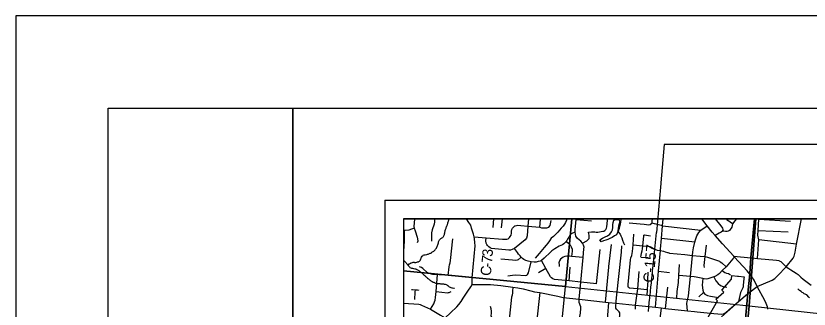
# Model space of a CAD drawing. Extents: x -8.2 to 38.5, y -0.1 to 21.9.
# Drawn here: x 0.063 to 4.362, y 20.274 to 21.864 of the extents above; entities that cross this region are included whole.
import ezdxf

# ---------------------------------------------------------------- set-up
doc = ezdxf.new("R2010")
doc.units = 0
for name, color, linetype in [('Default', 7, 'Continuous'), ('GM_X_Adjacent_County_Text', 7, 'Continuous'), ('GM_X_Airport_Location_Class_2', 7, 'Continuous'), ('GM_X_Airport_Location_Class_3', 7, 'Continuous'), ('GM_X_County', 7, 'Continuous'), ('GM_X_Minor_Lake', 7, 'Continuous'), ('GM_X_Minor_Lake_Text', 7, 'Continuous'), ('GM_X_Minor_River', 7, 'Continuous'), ('GM_X_Section', 7, 'Continuous'), ('GM_X_Township', 7, 'Continuous'), ('GM_X_Township_Subdivision_Text', 7, 'Continuous'), ('GM_X_Township_Text', 7, 'Continuous')]:
    doc.layers.add(name, color=color, linetype=linetype)

msp = doc.modelspace()

# ---------------------------------------------------------------- linework, layer by layer
at = {"layer": 'Default'}
for points in [[(8.9634, 21.1673), (3.5768, 21.1673), (3.5587, 20.9592), (3.5579, 20.9504), (3.5571, 20.9409), (3.557, 20.9403), (3.5565, 20.9346), (3.5354, 20.6894), (3.5327, 20.6897), (3.5152, 20.5087), (3.514, 20.4975), (3.5122, 20.481), (3.5118, 20.4768), (3.5106, 20.466), (3.5092, 20.4518), (3.5081, 20.4422), (3.5079, 20.44), (3.5067, 20.4286), (3.5055, 20.4169), (3.5042, 20.4045), (3.5032, 20.3958), (3.5024, 20.388), (3.5012, 20.3763), (3.4999, 20.3644), (3.4987, 20.3529), (3.4972, 20.3387), (3.4965, 20.3322), (3.4956, 20.3236), (3.494, 20.3078), (3.4939, 20.3071), (3.4918, 20.2869), (3.489, 20.2612)], [(3.7486, 17.3899), (3.8184, 18.0516), (3.8435, 18.2895), (3.8449, 18.303), (3.8472, 18.3279), (3.8854, 18.7517), (3.9289, 19.2353), (3.9436, 19.3979), (3.9961, 19.9817), (4.0302, 20.3597), (4.0404, 20.4649), (4.0467, 20.5533), (4.0665, 20.7635), (4.0666, 20.7645), (2.1634, 20.7645), (2.1634, 15.4317)], [(8.9634, 15.3136), (8.9634, 20.7535), (8.8842, 20.7645), (4.0666, 20.7645), (4.0665, 20.7635), (4.0467, 20.5533), (4.0404, 20.4649), (4.0302, 20.3597), (3.9961, 19.9817), (3.9436, 19.3979), (3.9289, 19.2353), (3.8854, 18.7517), (3.8472, 18.3279), (3.8449, 18.303), (3.8435, 18.2895), (3.8184, 18.0516), (3.7486, 17.3899)], [(3.8148, 20.2303), (3.8651, 20.3183), (3.859, 20.3257), (3.8572, 20.3279), (3.8855, 20.353), (3.8997, 20.3656), (3.8894, 20.3771), (3.9415, 20.4374), (3.9437, 20.456), (3.9743, 20.4531), (3.9791, 20.4526), (4.0097, 20.4497), (4.0088, 20.4408), (4.0086, 20.4392), (4.005, 20.4034), (4.0044, 20.3971), (4.0042, 20.3951), (4.0036, 20.3893), (3.9899, 20.3651), (3.98, 20.3157), (3.9795, 20.3133), (3.8874, 20.2316)]]:
    msp.add_lwpolyline(points, dxfattribs=at)
for points in [[(3.0765, 20.7645), (2.1634, 20.7645), (2.1634, 20.4819), (3.0413, 20.3975)], [(4.0738, 20.7645), (3.0765, 20.7645), (3.0413, 20.3975), (4.0367, 20.2914)], [(5.1033, 20.7645), (4.0738, 20.7645), (4.0367, 20.2914), (5.0467, 20.1811)], [(2.1634, 20.4819), (2.1634, 19.4712), (2.9408, 19.3823), (3.0413, 20.3975)]]:
    msp.add_lwpolyline(points, close=True, dxfattribs=at)
at = {"layer": 'GM_X_Adjacent_County_Text'}
for points in [[(3.0413, 20.3975), (4.0367, 20.2914), (3.9431, 19.2991), (2.9408, 19.3823)], [(5.0467, 20.1811), (4.9457, 19.1792), (3.9431, 19.2991), (4.0367, 20.2914)]]:
    msp.add_lwpolyline(points, close=True, dxfattribs=at)
at = {"layer": 'GM_X_Airport_Location_Class_2'}
for p, q in [((2.6514, 20.7645), (2.6475, 20.7165)), ((2.6989, 20.7645), (2.6941, 20.7153)), ((2.9021, 20.7177), (2.9058, 20.7604)), ((3.0994, 20.7593), (3.1835, 20.7536)), ((2.1634, 20.6425), (2.1676, 20.6423)), ((3.2101, 20.4104), (3.2288, 20.5982)), ((2.9357, 20.495), (2.8955, 20.47)), ((3.0619, 20.4273), (3.0678, 20.5019)), ((3.2583, 20.3122), (3.2772, 20.5021)), ((3.2757, 20.3104), (3.2633, 20.1713))]:
    msp.add_line(p, q, dxfattribs=at)
for points in [[(2.2235, 20.7645), (2.2215, 20.7396), (2.2202, 20.7231), (2.2221, 20.7122), (2.2268, 20.6995), (2.2377, 20.6645), (2.2405, 20.6553), (2.2408, 20.642), (2.2387, 20.6341)], [(2.3333, 20.7645), (2.3325, 20.7561), (2.3318, 20.7476), (2.3307, 20.7345), (2.3198, 20.7033), (2.3163, 20.6871), (2.3162, 20.6712), (2.315, 20.6587), (2.3157, 20.6427)], [(2.8422, 20.7645), (2.8382, 20.7234), (2.8333, 20.6724), (2.8299, 20.6584), (2.8236, 20.6495), (2.7647, 20.6033), (2.7531, 20.5967), (2.7441, 20.594), (2.7345, 20.5935), (2.6409, 20.6035), (2.6336, 20.6065), (2.6271, 20.6112), (2.6194, 20.6184), (2.615, 20.6249), (2.6115, 20.6314), (2.6103, 20.6441), (2.6117, 20.6611)], [(3.1167, 20.328), (3.1251, 20.4205), (3.1369, 20.5541), (3.1419, 20.6014), (3.1425, 20.6102), (3.139, 20.6215), (3.1331, 20.6312), (3.1241, 20.6432), (3.1064, 20.6577), (3.0987, 20.6704), (3.0938, 20.6911), (3.0947, 20.704), (3.0994, 20.7593), (3.0998, 20.7645)], [(3.1331, 20.6312), (3.1581, 20.6447), (3.1654, 20.651), (3.1702, 20.6571), (3.1698, 20.6666), (3.1697, 20.6758), (3.168, 20.683), (3.1668, 20.6922), (3.1834, 20.6933), (3.1942, 20.6933), (3.2003, 20.6927), (3.208, 20.6919), (3.213, 20.6915), (3.2178, 20.6919), (3.2447, 20.696), (3.25, 20.6977), (3.2541, 20.6998), (3.2574, 20.7025), (3.26, 20.7054), (3.2626, 20.7094), (3.2645, 20.7139), (3.266, 20.7203), (3.2695, 20.7542), (3.2698, 20.7585), (3.2695, 20.7612), (3.2683, 20.7645)], [(3.5112, 20.7409), (3.5119, 20.7512), (3.513, 20.7645)], [(2.5468, 20.6666), (2.6117, 20.6611), (2.7, 20.6541), (2.7129, 20.6531), (2.7242, 20.6541), (2.7315, 20.6559), (2.7379, 20.6616), (2.7427, 20.6671), (2.7467, 20.6758), (2.7485, 20.6851), (2.7498, 20.6977), (2.7516, 20.705), (2.7524, 20.7094), (2.7546, 20.7136), (2.7584, 20.7174), (2.7616, 20.7212), (2.7678, 20.725)], [(2.7678, 20.725), (2.7685, 20.7255), (2.7766, 20.7281), (2.7829, 20.7287), (2.7989, 20.7281), (2.8382, 20.7234), (2.9021, 20.7177), (2.9124, 20.7157), (2.9238, 20.7147), (2.9347, 20.7145), (2.9408, 20.7151), (2.9519, 20.7193), (2.9588, 20.7272), (2.9612, 20.7361), (2.9647, 20.7547)], [(3.5112, 20.7409), (3.501, 20.732), (3.4934, 20.7295), (3.4815, 20.7311), (3.4675, 20.7322), (3.4473, 20.7344), (3.3876, 20.7403)], [(3.5683, 20.7261), (3.5242, 20.7363), (3.5112, 20.7409)], [(2.2221, 20.7122), (2.1926, 20.7031), (2.1747, 20.701), (2.1682, 20.7014), (2.1634, 20.7017)], [(2.1682, 20.7014), (2.1676, 20.6423), (2.1634, 20.5891)], [(3.0938, 20.6911), (3.0792, 20.6866), (3.0717, 20.6815), (3.0671, 20.6772), (3.0592, 20.6649), (3.0528, 20.6531), (3.0511, 20.6496)], [(3.4842, 20.3782), (3.4325, 20.3839), (3.3878, 20.3881), (3.3825, 20.3918), (3.3814, 20.3964), (3.382, 20.4075), (3.392, 20.522), (3.3943, 20.5412), (3.3962, 20.5518), (3.4004, 20.5641), (3.4051, 20.5863), (3.4092, 20.6236), (3.4118, 20.6807)], [(2.4063, 20.4569), (2.4108, 20.5026), (2.4135, 20.5151), (2.4173, 20.5244), (2.4189, 20.5377), (2.431, 20.6555)], [(3.0511, 20.6496), (3.0495, 20.646), (3.0459, 20.6403), (3.0337, 20.6277), (3.0249, 20.6224), (3.0074, 20.6149), (2.9832, 20.6017), (2.968, 20.5901), (2.9598, 20.5835), (2.9256, 20.5502), (2.9114, 20.5385), (2.9039, 20.5343), (2.8943, 20.5316), (2.8833, 20.5296), (2.8712, 20.5296), (2.8554, 20.5313), (2.8398, 20.5346), (2.8276, 20.5379), (2.8158, 20.5435), (2.8089, 20.548), (2.8015, 20.5553), (2.7956, 20.5636), (2.7877, 20.5725), (2.7814, 20.5816), (2.7647, 20.6033)], [(3.0459, 20.6403), (3.0573, 20.6318), (3.0663, 20.6226), (3.0729, 20.6114), (3.0772, 20.599), (3.0775, 20.5882), (3.0751, 20.5601)], [(3.4894, 20.553), (3.4522, 20.5549), (3.4507, 20.5583), (3.4522, 20.5644), (3.4543, 20.5782), (3.4566, 20.5896), (3.4599, 20.6013), (3.4617, 20.6172), (3.4658, 20.67), (3.4668, 20.6746), (3.4697, 20.6764), (3.5028, 20.6718)], [(3.2772, 20.5021), (3.2775, 20.5051), (3.2912, 20.6254)], [(3.3169, 20.3159), (3.3186, 20.3349), (3.3448, 20.5828), (3.3479, 20.6175)], [(3.4092, 20.6236), (3.4617, 20.6172), (3.4873, 20.6153), (3.4989, 20.6133), (3.5076, 20.6099), (3.5187, 20.6031), (3.5292, 20.5967), (3.5378, 20.5939), (3.556, 20.5928)], [(2.8015, 20.5553), (2.7855, 20.5415), (2.7803, 20.5388), (2.7714, 20.5376), (2.7549, 20.5391), (2.691, 20.5444)], [(3.1369, 20.5541), (3.0751, 20.5601), (3.0634, 20.561), (3.0487, 20.5616), (3.0388, 20.5595), (3.0298, 20.5558), (3.0215, 20.5509), (3.0147, 20.5448), (3.009, 20.5365), (3.0063, 20.5255), (3.0071, 20.5161), (3.0084, 20.5052)], [(2.7298, 20.4539), (2.754, 20.4576), (2.7714, 20.4597), (2.8275, 20.4562), (2.8317, 20.458), (2.8356, 20.4613), (2.8415, 20.4707), (2.8554, 20.5313)], [(3.2101, 20.4104), (3.1251, 20.4205), (3.0619, 20.4273), (2.9829, 20.4355), (2.9735, 20.4381), (2.9661, 20.4438), (2.9614, 20.4497), (2.9357, 20.495), (2.9114, 20.5385)], [(2.3581, 20.4607), (2.3485, 20.4612), (2.3226, 20.4616), (2.3031, 20.4667), (2.2926, 20.4729), (2.2691, 20.4944), (2.2612, 20.4995), (2.2506, 20.5027)], [(3.4393, 20.4772), (3.4325, 20.3839), (3.4194, 20.2958)], [(3.4878, 20.4745), (3.4854, 20.4338), (3.4881, 20.4243), (3.4867, 20.4082), (3.4842, 20.3782), (3.4817, 20.3482)], [(2.3101, 20.2742), (2.3284, 20.3026), (2.3325, 20.3137), (2.3347, 20.3228), (2.3373, 20.3376), (2.3402, 20.3699), (2.3485, 20.4612)], [(2.5364, 20.4439), (2.4063, 20.4569), (2.3782, 20.4597), (2.3581, 20.4607)], [(2.7563, 20.3938), (2.7551, 20.3718), (2.7545, 20.363), (2.7524, 20.3494), (2.749, 20.3391), (2.7302, 20.1485)], [(2.3402, 20.3699), (2.4016, 20.3631), (2.4077, 20.3637), (2.4111, 20.3651), (2.4215, 20.3705)], [(2.9036, 20.3635), (2.8852, 20.2003), (2.8761, 20.1127), (2.8707, 20.0414)], [(3.0263, 20.1974), (3.0546, 20.1948), (3.0702, 20.1932), (3.0822, 20.1942), (3.1012, 20.2028), (3.1098, 20.2103), (3.1169, 20.2221), (3.1202, 20.2344), (3.1224, 20.2523), (3.1252, 20.2786), (3.1245, 20.2864), (3.1158, 20.3093), (3.1155, 20.3179), (3.1167, 20.328)], [(3.325, 20.1305), (3.3364, 20.2437), (3.3356, 20.2543), (3.3335, 20.2592), (3.3239, 20.2683), (3.3186, 20.2745), (3.315, 20.2795), (3.314, 20.2859), (3.3145, 20.296), (3.316, 20.3063), (3.3169, 20.3159)], [(3.4194, 20.2958), (3.4186, 20.2812), (3.4202, 20.2735)], [(3.56, 20.2807), (3.5506, 20.2077), (3.5543, 20.1645), (3.5675, 20.1268)]]:
    msp.add_lwpolyline(points, dxfattribs=at)
at = {"layer": 'GM_X_Airport_Location_Class_3'}
for points in [[(4.081, 20.3972), (4.0639, 20.4303), (4.0523, 20.4483), (4.0406, 20.4643), (4.0259, 20.4823), (3.9585, 20.5554), (3.9535, 20.5613), (3.8921, 20.629), (3.8525, 20.6729), (3.8364, 20.6916), (3.8104, 20.726), (3.7812, 20.7645)], [(4.1378, 20.2731), (4.1358, 20.2873), (4.1301, 20.3044), (4.1227, 20.3202), (4.081, 20.3972)]]:
    msp.add_lwpolyline(points, dxfattribs=at)
at = {"layer": 'GM_X_County'}
for points in [[(0.5634, 21.3645), (1.5634, 21.3645), (1.5634, 0.3645), (0.5634, 0.3645)], [(1.5634, 21.3645), (33.5634, 21.3645), (33.5634, 0.3645), (1.5634, 0.3645)]]:
    msp.add_lwpolyline(points, close=True, dxfattribs=at)
at = {"layer": 'GM_X_Minor_Lake_Text'}
for points in [[(3.3233, 20.689), (3.3179, 20.6767), (3.3075, 20.6709), (3.2952, 20.6624), (3.2825, 20.657), (3.2718, 20.6523), (3.2596, 20.6476), (3.2481, 20.6449), (3.2351, 20.6398), (3.2285, 20.6502), (3.2427, 20.6594), (3.2573, 20.6663), (3.2703, 20.6721), (3.2819, 20.6802), (3.2913, 20.6925), (3.2969, 20.7049), (3.2975, 20.7174), (3.2986, 20.7303), (3.3, 20.7436), (3.3045, 20.756), (3.3171, 20.7599), (3.3304, 20.76), (3.3355, 20.7489), (3.3329, 20.736), (3.3292, 20.7236), (3.3274, 20.7114)], [(3.3274, 20.7114), (3.3233, 20.689)]]:
    msp.add_lwpolyline(points, dxfattribs=at)
at = {"layer": 'GM_X_Minor_River'}
for points in [[(2.1902, 20.5095), (2.1926, 20.5191), (2.196, 20.5205), (2.2022, 20.5234), (2.2049, 20.5244), (2.2079, 20.5255), (2.2126, 20.5273), (2.2156, 20.5279), (2.2187, 20.5282), (2.2209, 20.5282), (2.2232, 20.5274), (2.2258, 20.5265), (2.2281, 20.5265), (2.2308, 20.5268), (2.2354, 20.5282), (2.2404, 20.5299), (2.2446, 20.5313), (2.2477, 20.5324), (2.2504, 20.5342), (2.2543, 20.5383), (2.2559, 20.542), (2.2576, 20.5462), (2.2592, 20.5507), (2.2616, 20.5564), (2.2644, 20.5605), (2.2683, 20.5638), (2.2714, 20.566), (2.276, 20.5677), (2.2821, 20.5691), (2.2913, 20.5707), (2.2944, 20.5714), (2.2974, 20.5717), (2.309, 20.5771), (2.312, 20.5782), (2.3163, 20.5799), (2.3175, 20.5826), (2.3283, 20.5876), (2.3295, 20.5902), (2.3353, 20.5962), (2.3381, 20.5987), (2.342, 20.6051), (2.3452, 20.6107), (2.3464, 20.613), (2.3485, 20.6198), (2.3498, 20.6232), (2.3522, 20.6277), (2.3531, 20.6341), (2.3535, 20.6368), (2.3536, 20.6398), (2.3548, 20.6428), (2.3565, 20.6466), (2.3592, 20.6503), (2.362, 20.6533), (2.3662, 20.6562), (2.3693, 20.6584), (2.3724, 20.6602), (2.3763, 20.6632), (2.379, 20.6654), (2.3802, 20.668), (2.383, 20.6717), (2.385, 20.6751), (2.3859, 20.6793), (2.3863, 20.6827), (2.3872, 20.6872), (2.3881, 20.691), (2.3885, 20.694), (2.3898, 20.6974), (2.3906, 20.7012), (2.3923, 20.7065), (2.3944, 20.7125), (2.3949, 20.7163), (2.3973, 20.7212), (2.3993, 20.7253), (2.4005, 20.7291), (2.4017, 20.7317), (2.4026, 20.734), (2.4034, 20.7378), (2.4047, 20.7419), (2.4063, 20.7468), (2.4076, 20.7502), (2.4084, 20.7529), (2.4092, 20.7559), (2.4097, 20.7597), (2.4102, 20.7627), (2.4105, 20.7645)], [(3.0507, 20.7645), (3.0479, 20.7558), (3.0423, 20.7445), (3.0363, 20.7344), (3.0292, 20.7235), (3.0191, 20.7124), (3.0089, 20.7016), (3.0003, 20.6919), (2.9894, 20.6811), (2.9766, 20.6678), (2.9634, 20.6582), (2.9555, 20.6451), (2.9468, 20.6312), (2.9374, 20.6201), (2.9257, 20.6082), (2.9081, 20.5858), (2.8987, 20.575), (2.8886, 20.5635), (2.878, 20.5504)], [(3.343, 20.7645), (3.3425, 20.7596), (3.3406, 20.7471), (3.3385, 20.735), (3.3351, 20.7218), (3.3326, 20.7116), (3.3285, 20.7018), (3.3233, 20.689)], [(3.3258, 20.6951), (3.3387, 20.6806), (3.3419, 20.6711), (3.3469, 20.6603), (3.3516, 20.648), (3.3569, 20.6338), (3.3612, 20.6227)], [(2.1634, 20.5395), (2.1638, 20.5393), (2.169, 20.5346), (2.1753, 20.5283), (2.1786, 20.5248), (2.1805, 20.5217), (2.183, 20.5178), (2.1849, 20.5155), (2.1885, 20.5112), (2.1941, 20.5053), (2.1963, 20.5037), (2.1989, 20.5002), (2.2041, 20.4974), (2.2068, 20.4962), (2.2098, 20.4954), (2.2121, 20.4957), (2.2174, 20.4948), (2.225, 20.4934), (2.2299, 20.4918), (2.2321, 20.4909), (2.2404, 20.4869), (2.2464, 20.4833), (2.2512, 20.4801), (2.2549, 20.477), (2.2572, 20.4754), (2.2598, 20.473), (2.2627, 20.4703), (2.2661, 20.4675), (2.2709, 20.464), (2.275, 20.4604), (2.2795, 20.4565), (2.2817, 20.4542), (2.2839, 20.4518), (2.2861, 20.4491), (2.2891, 20.4467), (2.2917, 20.444), (2.2928, 20.4417), (2.2991, 20.4381), (2.3029, 20.4353), (2.3055, 20.4337), (2.3077, 20.4314), (2.3118, 20.4282), (2.3148, 20.4255), (2.3189, 20.4238), (2.3242, 20.421), (2.3276, 20.4198), (2.3321, 20.4181), (2.3343, 20.4173), (2.3381, 20.4157), (2.3411, 20.4148), (2.3438, 20.414), (2.3483, 20.4135), (2.351, 20.4134), (2.3608, 20.4124), (2.3642, 20.4119), (2.3714, 20.4113), (2.3768, 20.4112), (2.3806, 20.4107), (2.384, 20.4102), (2.3893, 20.4093), (2.3945, 20.4069), (2.3979, 20.4056), (2.402, 20.4028), (2.4047, 20.4016), (2.4121, 20.3957), (2.417, 20.3929), (2.4211, 20.3913), (2.426, 20.39), (2.4287, 20.3899), (2.4362, 20.3874), (2.4396, 20.3873)], [(4.3632, 20.3348), (4.3596, 20.3395), (4.3488, 20.3508), (4.3346, 20.3577), (4.3293, 20.3616), (4.3249, 20.3644), (4.3182, 20.3696), (4.3103, 20.3755), (4.3055, 20.3791), (4.3007, 20.3841)], [(2.7049, 20.1402), (2.6655, 20.1994), (2.6536, 20.2122), (2.6437, 20.2258), (2.6398, 20.2384), (2.6413, 20.2513), (2.6416, 20.2635), (2.6392, 20.2749), (2.6346, 20.2883)]]:
    msp.add_lwpolyline(points, dxfattribs=at)
at = {"layer": 'GM_X_Section'}
msp.add_lwpolyline([(0.0634, -0.1355), (34.0634, -0.1355), (34.0634, 21.8645), (0.0634, 21.8645)], close=True, dxfattribs=at)
msp.add_lwpolyline([(8.9634, 15.3136), (8.9634, 20.7645), (2.1634, 20.7645), (2.1634, 13.9645)], dxfattribs=at)
at = {"layer": 'GM_X_Township'}
for p, q in [((2.0634, 20.8645), (9.0634, 20.8645)), ((2.0634, 20.8645), (2.0634, 13.8645)), ((2.1634, 20.7645), (2.1634, 13.9645)), ((2.1634, 20.7645), (8.9634, 20.7645))]:
    msp.add_line(p, q, dxfattribs=at)
at = {"layer": 'GM_X_Township_Subdivision_Text'}
for p, q in [((4.0851, 20.7004), (4.2489, 20.6931)), ((3.7423, 20.6363), (3.5619, 20.6564)), ((4.2941, 20.6269), (4.0893, 20.6492)), ((3.5464, 20.4794), (3.6046, 20.4733)), ((3.5835, 20.2782), (3.5969, 20.3926)), ((3.7904, 20.3645), (3.764, 20.3416))]:
    msp.add_line(p, q, dxfattribs=at)
for points in [[(3.9676, 20.7645), (3.9601, 20.752), (3.9471, 20.7371), (3.9429, 20.7194), (3.9299, 20.7011), (3.9258, 20.6981), (3.925, 20.6975), (3.9184, 20.6949), (3.9135, 20.695), (3.9085, 20.6948), (3.8995, 20.697), (3.8929, 20.6967), (3.8848, 20.6916), (3.874, 20.6858), (3.8525, 20.6729)], [(3.8929, 20.6967), (3.8954, 20.7054), (3.8945, 20.7126), (3.8853, 20.7262), (3.8545, 20.7645)], [(3.9471, 20.7371), (3.9221, 20.7545), (3.9134, 20.7645)], [(4.0445, 20.7645), (4.0668, 20.763), (4.0888, 20.7615), (4.2618, 20.7502)], [(4.0818, 20.5491), (4.0893, 20.6492), (4.0835, 20.6748), (4.0851, 20.7004), (4.0888, 20.7615), (4.0889, 20.7645)], [(3.5683, 20.7261), (3.7752, 20.7016), (3.8104, 20.726)], [(3.7033, 20.2651), (3.6989, 20.3049), (3.7007, 20.3163), (3.7045, 20.3302), (3.7083, 20.3453), (3.7187, 20.4516), (3.7298, 20.5654), (3.7317, 20.5841), (3.7357, 20.6072), (3.7423, 20.6363), (3.7455, 20.6502), (3.7532, 20.6709), (3.7643, 20.6889), (3.7752, 20.7016)], [(3.556, 20.5928), (3.5725, 20.5885), (3.5827, 20.5855), (3.5947, 20.582), (3.5971, 20.581), (3.6018, 20.5787), (3.6053, 20.5774), (3.688, 20.5694), (3.7298, 20.5654), (3.7707, 20.5615), (3.7975, 20.5589), (3.7986, 20.5587), (3.8115, 20.5563), (3.876, 20.5341), (3.8797, 20.5314), (3.8881, 20.5244), (3.9118, 20.5041)], [(3.7949, 20.4997), (3.7925, 20.51), (3.7986, 20.5587), (3.8063, 20.6214)], [(3.9585, 20.5554), (3.9479, 20.5462), (3.9118, 20.5041), (3.8907, 20.4827), (3.8758, 20.4676), (3.8669, 20.4595), (3.8507, 20.4516), (3.8451, 20.4496), (3.8136, 20.4384), (3.804, 20.4368), (3.7934, 20.4389), (3.7858, 20.4404), (3.7503, 20.4472), (3.7397, 20.449), (3.7187, 20.4516), (3.6558, 20.4561)], [(3.6449, 20.3336), (3.6473, 20.3704), (3.6535, 20.4193), (3.6558, 20.4561), (3.6596, 20.5152)], [(3.8907, 20.4827), (3.9056, 20.473), (3.915, 20.4689), (3.9245, 20.4664), (3.9368, 20.46)], [(3.7858, 20.4404), (3.7816, 20.4047), (3.7858, 20.3764), (3.7904, 20.3645), (3.7971, 20.3556), (3.8117, 20.3481), (3.8268, 20.3443), (3.8707, 20.3371)], [(3.8451, 20.4496), (3.8573, 20.4267), (3.8695, 20.4123), (3.8822, 20.4029), (3.8961, 20.3972), (3.9169, 20.3937)]]:
    msp.add_lwpolyline(points, dxfattribs=at)
at = {"layer": 'GM_X_Township_Text'}
msp.add_line((4.035, 20.3626), (4.081, 20.3972), dxfattribs=at)
for points in [[(2.5359, 20.4072), (2.5364, 20.4439), (2.5515, 20.6175), (2.5512, 20.6346), (2.5496, 20.6555), (2.5468, 20.6666), (2.5432, 20.6808), (2.5331, 20.7123), (2.528, 20.7288), (2.5171, 20.7443), (2.5048, 20.7645)], [(3.5298, 20.284), (3.5464, 20.4794), (3.556, 20.5928), (3.5565, 20.5988), (3.5619, 20.6564), (3.5683, 20.7261), (3.5718, 20.7645)], [(4.081, 20.3972), (4.1617, 20.4319), (4.1764, 20.4404), (4.1921, 20.4567), (4.2384, 20.5036), (4.2747, 20.551), (4.2808, 20.5614), (4.2856, 20.5825), (4.2941, 20.6269), (4.3205, 20.7645)], [(3.9535, 20.5613), (4.0469, 20.5527), (4.0519, 20.5522)], [(4.0519, 20.5522), (4.0818, 20.5491), (4.1847, 20.5399), (4.1974, 20.5371), (4.2003, 20.5357)], [(4.2003, 20.5357), (4.2079, 20.5322), (4.2384, 20.5036), (4.2523, 20.4937), (4.2636, 20.4863), (4.2772, 20.4784), (4.2914, 20.4695), (4.3027, 20.461), (4.3174, 20.4469), (4.3297, 20.436), (4.3723, 20.4039)], [(2.3391, 20.1402), (2.3439, 20.1541), (2.351, 20.1716), (2.3599, 20.188), (2.3671, 20.1994), (2.3749, 20.2098), (2.3893, 20.2262), (2.4183, 20.254), (2.4522, 20.2863), (2.4644, 20.2991), (2.4765, 20.3163), (2.4879, 20.3334), (2.513, 20.3716), (2.528, 20.3945), (2.5359, 20.4072)], [(2.5359, 20.4072), (2.5615, 20.4075), (2.6104, 20.4083), (2.6359, 20.4068), (2.6918, 20.4023), (2.7563, 20.3938), (2.7839, 20.3897), (2.8123, 20.3835), (2.8541, 20.373), (2.8742, 20.3687), (2.9036, 20.3635), (3.0003, 20.3445), (3.0293, 20.3379), (3.1167, 20.328), (3.2583, 20.3122), (3.2757, 20.3104), (3.316, 20.3063), (3.4194, 20.2958), (3.4578, 20.2919), (3.5298, 20.284)], [(3.5298, 20.284), (3.56, 20.2807), (3.5835, 20.2782), (3.7033, 20.2651), (3.7417, 20.261), (3.7549, 20.2597), (3.8452, 20.2511), (3.8893, 20.2469), (3.8973, 20.2478), (3.9105, 20.2557), (3.9264, 20.2695), (4.0304, 20.3592), (4.035, 20.3626)], [(2.1634, 20.3061), (2.2462, 20.3004), (2.2545, 20.299), (2.262, 20.2961), (2.3101, 20.2742), (2.3648, 20.2415), (2.3893, 20.2262)]]:
    msp.add_lwpolyline(points, dxfattribs=at)

# ---------------------------------------------------------------- texts
at = {"layer": 'GM_X_Minor_Lake'}
for s, height, rotation, p in [('3', 0.0568, 85.4115, (2.6462, 20.5568)), ('C-157', 0.05682, 84.9566, (3.5187, 20.416)), ('7', 0.0568, 85.1157, (2.6432, 20.5219)), ('C', 0.0568, 85.044, (2.6372, 20.4526)), ('-', 0.0568, 85.0645, (2.6412, 20.4988)), ('T', 0.0568, 356.2244, (2.2008, 20.3262))]:
    msp.add_text(s, height=height, rotation=rotation, dxfattribs=at).set_placement(p)

doc.saveas('drawing.dxf')
